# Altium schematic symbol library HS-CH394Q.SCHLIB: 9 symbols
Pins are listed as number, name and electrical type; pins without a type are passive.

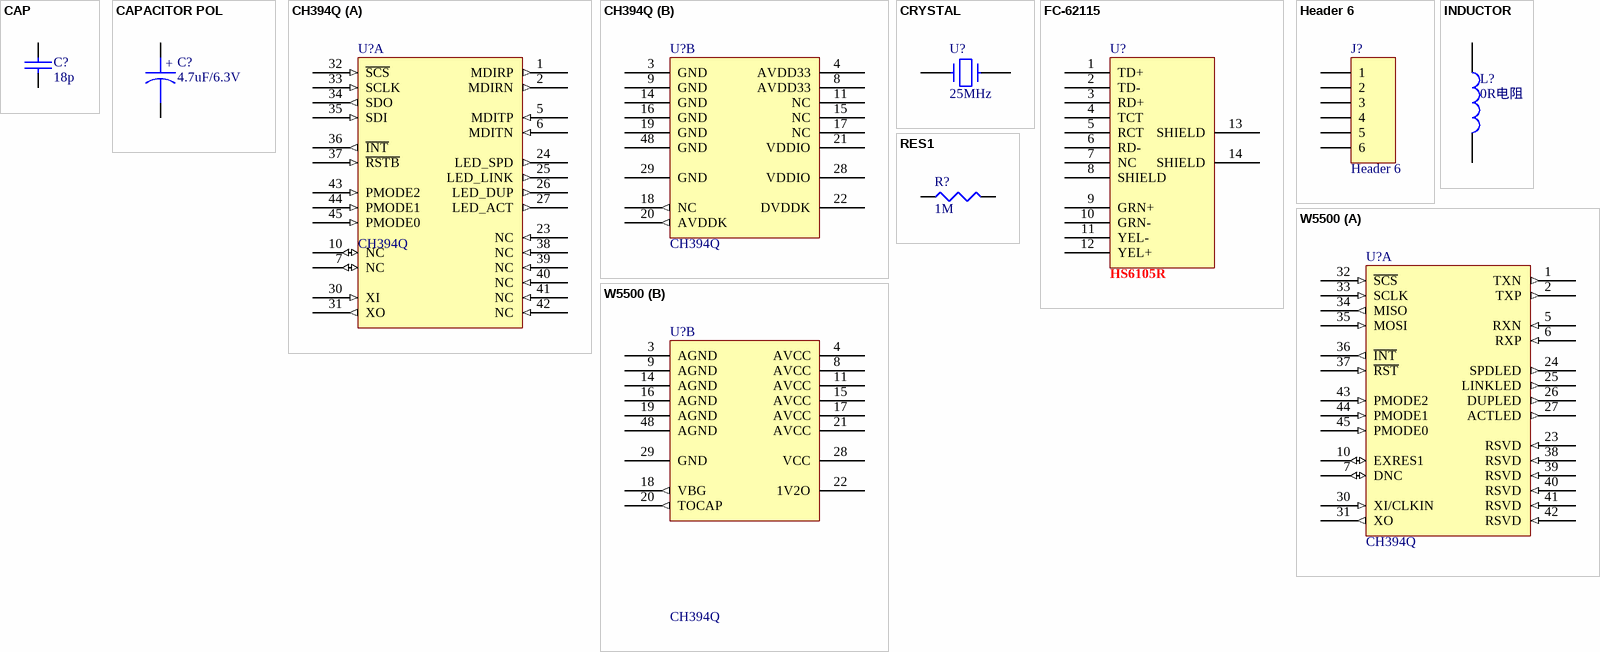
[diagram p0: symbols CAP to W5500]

## CAP
designator C?, comment 18p
Capacitor
footprint 0402
footprint 0603
pins: 1, 2

## CAPACITOR POL
designator C?, comment 4.7uF/6.3V
Capacitor
footprint 3216
pins: 1, 2

## CH394Q
designator U?
footprint LQFP-48
footprint LQFP48
part A pins: 1 MDIRP (out), 2 MDIRN (out), 5 MDITP (in), 6 MDITN (in), 7 NC (io), 10 NC (io), 23 NC (in), 24 LED_SPD (out), 25 LED_LINK (out), 26 LED_DUP (out), 27 LED_ACT (out), 30 XI (in), 31 XO (out), 32 ~{SCS} (in), 33 SCLK (in), 34 SDO (out), 35 SDI (in), 36 ~{INT} (out), 37 ~{RSTB} (in), 38 NC (in), 39 NC (in), 40 NC (in), 41 NC (in), 42 NC (in), 43 PMODE2 (in), 44 PMODE1 (in), 45 PMODE0 (in)
part B pins: 3 GND (power), 4 AVDD33 (power), 8 AVDD33 (power), 9 GND (power), 11 NC (power), 14 GND (power), 15 NC (power), 16 GND (power), 17 NC (power), 18 NC (out), 19 GND (power), 20 AVDDK (out), 21 VDDIO (power), 22 DVDDK (power), 28 VDDIO (power), 29 GND (power), 48 GND (power)

## CRYSTAL
designator U?, comment 25MHz
Crystal
footprint XTAL - 49S
pins: 1, 2

## FC-62115
designator U?, comment HS6105R
footprint RJ45
footprint RJ45-2
pins: 1 TD+, 2 TD-, 3 RD+, 4 TCT, 5 RCT, 6 RD-, 7 NC, 8 SHIELD, 9 GRN+, 10 GRN-, 11 YEL-, 12 YEL+, 13 SHIELD, 14 SHIELD

## Header 6
designator J?
Header, 6-Pin
footprint SIP6
pins: 1, 2, 3, 4, 5, 6

## INDUCTOR
designator L?, comment 0R电阻
footprint 0603
pins: 1, 2

## RES1
designator R?, comment 1M
footprint 0402
footprint 0603
pins: 1, 2

## W5500
designator U?, comment CH394Q
W5500
footprint LQFP-48
footprint LQFP48
part A pins: 1 TXN (out), 2 TXP (out), 5 RXN (in), 6 RXP (in), 7 DNC (io), 10 EXRES1 (io), 23 RSVD (in), 24 SPDLED (out), 25 LINKLED (out), 26 DUPLED (out), 27 ACTLED (out), 30 XI/CLKIN (in), 31 XO (out), 32 ~{SCS} (in), 33 SCLK (in), 34 MISO (out), 35 MOSI (in), 36 ~{INT} (out), 37 ~{RST} (in), 38 RSVD (in), 39 RSVD (in), 40 RSVD (in), 41 RSVD (in), 42 RSVD (in), 43 PMODE2 (in), 44 PMODE1 (in), 45 PMODE0 (in)
part B pins: 3 AGND (power), 4 AVCC (power), 8 AVCC (power), 9 AGND (power), 11 AVCC (power), 14 AGND (power), 15 AVCC (power), 16 AGND (power), 17 AVCC (power), 18 VBG (out), 19 AGND (power), 20 TOCAP (out), 21 AVCC (power), 22 1V2O (power), 28 VCC (power), 29 GND (power), 48 AGND (power)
